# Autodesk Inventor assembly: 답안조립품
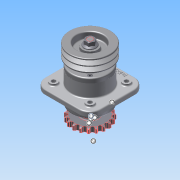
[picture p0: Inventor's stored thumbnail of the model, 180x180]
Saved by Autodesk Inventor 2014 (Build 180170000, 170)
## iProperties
Created: 2015-09
Part Number: 답안조립품
Document SubType Name: Assembly
Designer: study
Author: study
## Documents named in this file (12)
- C:\Users\study\Desktop\450909V1018\답안조립품.iam
- C:\Users\study\Desktop\450909V1018\1-본체.ipt
- C:\Users\study\Desktop\450909V1018\6-베어링 6206.ipt
- C:\Users\study\Desktop\450909V1018\3-축.ipt
- C:\Users\study\Desktop\450909V1018\9-M16-너트.ipt
- C:\Users\study\Desktop\450909V1018\2-커버.ipt
- C:\Users\study\Desktop\450909V1018\8-오일실 30x42.ipt
- C:\Users\study\Desktop\450909V1018\11-키 6x6.ipt
- C:\Users\study\Desktop\450909V1018\4-V벨트풀리.ipt
- C:\Users\study\Desktop\450909V1018\5-체인 스프로킷.ipt
- C:\Users\study\Desktop\450909V1018\10-M6.ipt
- C:\Users\study\Desktop\450909V1018\7-부시.ipt
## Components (23 placed, 11 different names)
1. 1-본체:1
2. 6-베어링 6206:1
3. 6-베어링 6206:2
4. 3-축:1 — 각도:1, 각도:2, 각도:5, 각도:6
5. 9-M16 너트:1 — 각도:6
6. 9-M16 너트:2 — 각도:5
7. 2-커버:1
8. 2-커버:2
9. 8-8-오일실 30x42:1
10. 8-8-오일실 30x42:2
11. 11-키 6x6:1 — 각도:1, 각도:3
12. 11-키 6x6:2 — 각도:2, 각도:4
13. 4-V벨트풀리:1 — 각도:3
14. 5-체인 스프로킷:1 — 각도:4
15. 7-부시:1
16. 10-M6:1
17. 10-M6:3
18. 10-M6:4
19. 10-M6:5
20. 10-M6:2
21. 10-M6:6
22. 10-M6:7
23. 10-M6:8
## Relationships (6: Angle 6)
- 각도:1 [Angle]: 3-축:1 ↔ 11-키 6x6:1
- 각도:2 [Angle]: 3-축:1 ↔ 11-키 6x6:2
- 각도:3 [Angle]: 11-키 6x6:1 ↔ 4-V벨트풀리:1
- 각도:4 [Angle]: 11-키 6x6:2 ↔ 5-체인 스프로킷:1
- 각도:5 [Angle]: 3-축:1 ↔ 9-M16 너트:2
- 각도:6 [Angle]: 3-축:1 ↔ 9-M16 너트:1
